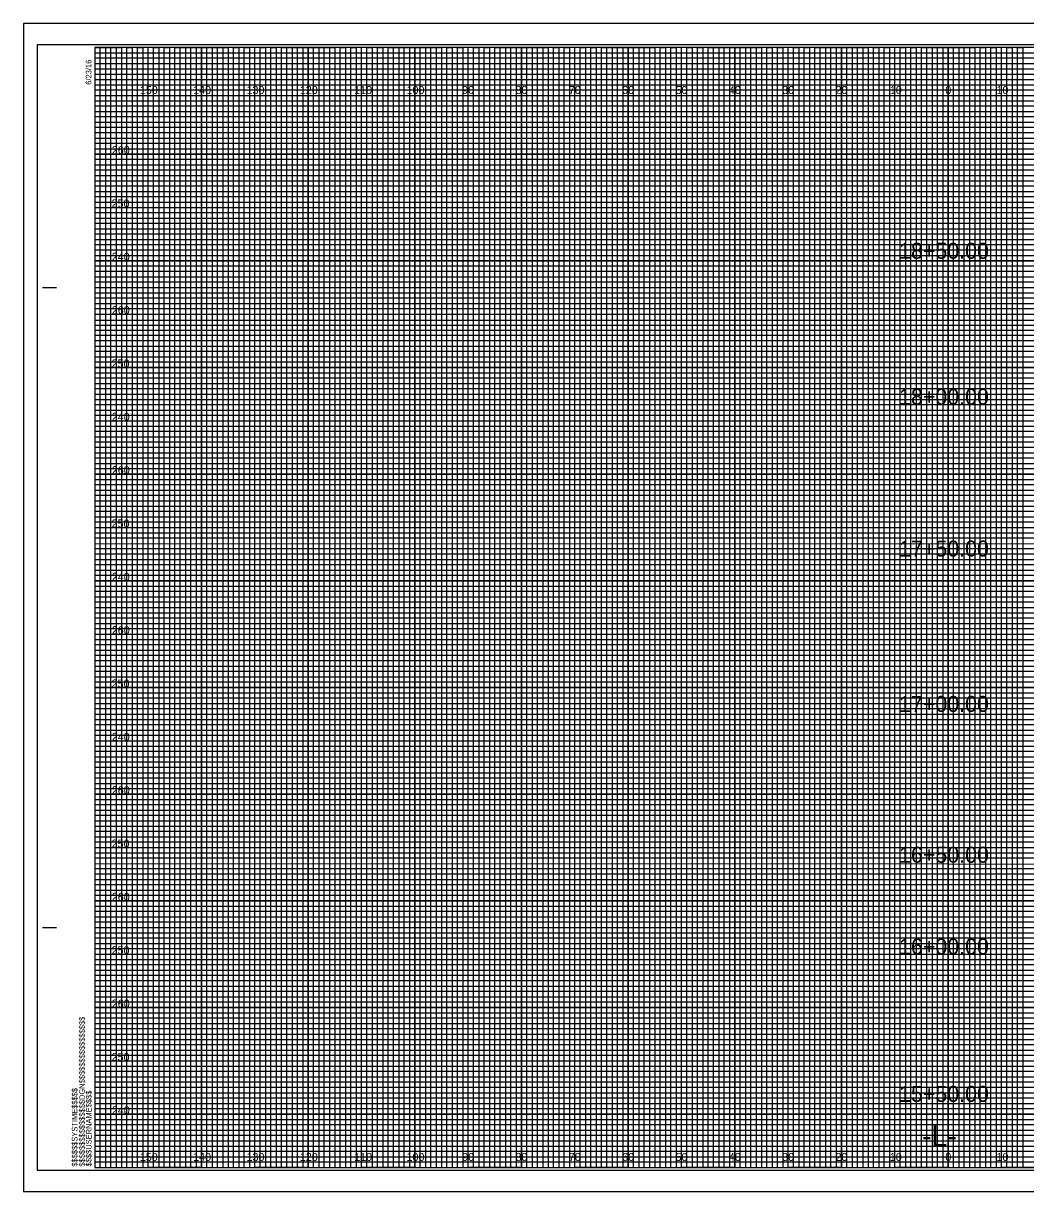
# Model space of a CAD drawing. Extents: x -13 to 359, y -5 to 2854.
# Drawn here: x -13.4 to 174.5, y -4.5 to 214.5 of the extents above; entities that cross this region are included whole.
import ezdxf

# ---------------------------------------------------------------- set-up
doc = ezdxf.new("R2010")
doc.units = 0
for name, color, linetype in [('Exist Cross Section Cell', 7, 'Continuous'), ('Exist XS Ground Line', 7, 'Continuous'), ('Prop CMT Concrete Structures', 7, 'Continuous'), ('Prop CMT DNC', 7, 'Continuous'), ('Prop CMT Pvmt Course 1', 7, 'Continuous'), ('Prop CMT Pvmt Course 1 CG', 7, 'Continuous'), ('Prop CMT Pvmt Course 2', 7, 'Continuous'), ('Prop CMT Pvmt Course 3', 7, 'Continuous'), ('Prop CMT Pvmt Course 3 Wedge', 7, 'Continuous'), ('Prop CMT Shear Line', 7, 'Continuous'), ('Prop CMT Slope Grass', 7, 'Continuous'), ('Prop CMT Subgrade Earthwork', 7, 'Continuous'), ('Scratch_Level_0', 7, 'Continuous')]:
    doc.layers.add(name, color=color, linetype=linetype)

msp = doc.modelspace()

# ---------------------------------------------------------------- linework, layer by layer
at = {"layer": 'Exist XS Ground Line'}
for p, q in [((10, 210), (0, 210)), ((10, 0), (10, 210)), ((30, 210), (20, 210)), ((20, 210), (20, 0)), ((30, 0), (30, 210)), ((50, 210), (40, 210)), ((40, 210), (40, 0)), ((50, 0), (50, 210)), ((70, 210), (60, 210)), ((60, 210), (60, 0)), ((70, 0), (70, 210)), ((90, 210), (80, 210)), ((80, 210), (80, 0)), ((90, 0), (90, 210)), ((110, 210), (100, 210)), ((100, 210), (100, 0)), ((110, 0), (110, 210)), ((130, 210), (120, 210)), ((120, 210), (120, 0)), ((130, 0), (130, 210)), ((150, 210), (140, 210)), ((140, 210), (140, 0)), ((150, 0), (150, 210)), ((170, 210), (160, 210)), ((160, 210), (160, 0)), ((170, 0), (170, 210)), ((20, 0), (10, 0)), ((40, 0), (30, 0)), ((60, 0), (50, 0)), ((80, 0), (70, 0)), ((100, 0), (90, 0)), ((120, 0), (110, 0)), ((140, 0), (130, 0)), ((160, 0), (150, 0)), ((180, 0), (170, 0))]:
    msp.add_line(p, q, dxfattribs=at)
for points in [[(0, 200), (320, 200), (320, 190), (0, 190)], [(0, 180), (320, 180), (320, 170), (0, 170)], [(0, 160), (320, 160), (320, 150), (0, 150)], [(0, 140), (320, 140), (320, 130), (0, 130)], [(0, 120), (320, 120), (320, 110), (0, 110)], [(0, 100), (320, 100), (320, 90), (0, 90)], [(0, 80), (320, 80), (320, 70), (0, 70)], [(0, 60), (320, 60), (320, 50), (0, 50)], [(0, 40), (320, 40), (320, 30), (0, 30)], [(0, 20), (320, 20), (320, 10), (0, 10)]]:
    msp.add_lwpolyline(points, dxfattribs=at)
at = {"layer": 'Prop CMT Concrete Structures'}
for p, q in [((-9.8, 165), (-7.3, 165)), ((-9.7, 165), (-7.2, 165)), ((-9.8, 45), (-7.3, 45)), ((-9.7, 45), (-7.2, 45)), ((0, 0), (0, 0)), ((0, 0), (0, 0)), ((0, 0), (0, 0)), ((0, 0), (0, 0)), ((0, 0), (0, 0)), ((0, 0), (0, 0)), ((0, 0), (0, 0))]:
    msp.add_line(p, q, dxfattribs=at)
msp.add_lwpolyline([(320, 210), (0, 210), (0, 0), (320, 0)], close=True, dxfattribs=at)
at = {"layer": 'Prop CMT DNC'}
for p, q in [((323.3, 214.5), (-13.4, 214.5)), ((-13.4, 214.5), (-13.4, -4.5)), ((-13.4, -4.5), (323.3, -4.5))]:
    msp.add_line(p, q, dxfattribs=at)
at = {"layer": 'Prop CMT Pvmt Course 1'}
for p, q in [((0, 209), (260, 209)), ((260, 207.98), (0, 207.98)), ((0, 207.98), (0, 207)), ((0, 207), (260, 207)), ((260, 205.89), (0, 205.89)), ((0, 205.89), (0, 204)), ((0, 204), (320, 204))]:
    msp.add_line(p, q, dxfattribs=at)
for points in [[(0, 203), (270, 203), (320, 203), (320, 202), (0, 202)], [(0, 201), (320, 201), (320, 199), (0, 199)], [(0, 198), (320, 198), (320, 197), (0, 196.98)], [(0, 196), (320, 196), (320, 194), (0, 194)], [(0, 193), (320, 193), (320, 192), (0, 192)], [(0, 191), (320, 191), (320, 189), (0, 189)], [(0, 188), (320, 188), (320, 187), (0, 187)], [(0, 186), (320, 186), (320, 184), (0, 184)], [(0, 183), (320, 183), (320, 182), (0, 182)], [(0, 181), (320, 181), (320, 179), (0, 179)], [(0, 178), (320, 178), (320, 177), (0, 177)], [(0, 176), (320, 176), (320, 173.95), (320, 173), (320, 172), (0, 172)], [(0, 174), (320, 174), (320, 173), (0, 173)], [(0, 171), (320, 171), (320, 169), (0, 169.03)], [(0, 169.03), (320, 169), (320, 168), (0, 168)], [(0, 167), (320, 167), (320, 166), (0, 166)], [(0, 164), (320, 164), (320, 163), (0, 163)], [(0, 162), (320, 162), (320, 161), (0, 161)], [(-0.07, 158.89), (320, 158.89), (320, 157.88), (-0.07, 157.88)], [(0, 157), (320, 157), (320, 156), (0, 156)], [(0, 154), (320, 154), (320, 153), (0, 153)], [(0, 152), (320, 152), (320, 151), (0, 151)], [(0, 149), (320, 149), (320, 148), (0, 148)], [(0, 147), (320, 147), (320, 146), (0, 146)], [(0, 144), (320, 144), (320, 143), (0, 143)], [(0, 142), (320, 142), (320, 141), (0, 141)], [(0, 139), (320, 139), (319.99, 137.98), (0, 138)], [(0, 137), (320, 137), (320, 136), (0, 136)], [(0, 134), (320, 134), (320, 133), (0, 133)], [(0, 132), (320, 132), (320, 131), (0, 131)], [(0, 129), (320, 129), (320, 128), (0, 128)], [(0, 127), (320, 127), (320, 126), (0, 126)], [(0, 124), (320, 124), (320, 123), (0, 123)], [(0, 122), (320, 122), (320, 121), (0, 121)], [(0, 119), (320, 119), (320, 118), (0, 118)], [(0, 116.99), (320.07, 116.91), (320, 116), (0, 116)], [(0, 114), (320, 114), (320, 113), (0, 113)], [(0, 112), (320, 112), (320, 111), (0, 111)], [(0, 109), (320, 109), (320, 108), (0, 108)], [(0, 107), (320, 107), (320, 106), (0, 106)], [(0, 104), (320, 104), (320, 103), (0, 103)], [(0, 102), (320, 102), (320, 101), (0, 101)], [(0, 99), (320, 99), (320, 98), (0, 98)], [(0, 97), (320, 97), (320, 96), (0, 96)], [(0, 94), (320, 94), (320, 93), (0, 93)], [(0, 92), (320, 92), (320, 91), (0, 91)], [(0, 89), (320, 89), (320, 88), (0, 88)], [(0, 87), (320, 87), (320, 86), (0, 86)], [(0, 84), (320, 84), (320, 83), (0, 83)], [(0, 82), (320, 82), (320, 81), (0, 81)], [(0, 79), (320, 79), (319.99, 77.98), (0, 78)], [(0, 77), (320, 77), (320, 76), (0, 76)], [(0, 74), (320, 74), (320, 73), (0, 73)], [(0, 72), (320, 72), (320, 71), (0, 71)], [(0, 69), (320, 69), (320, 68), (0, 68)], [(0, 67), (320, 67), (320, 66), (0, 66)], [(0, 64), (320, 64), (320, 63), (0, 63)], [(0, 62), (320, 62), (320, 61), (0, 61)], [(0, 59), (320, 59), (320, 58), (0, 58)], [(0, 56.99), (320.07, 56.91), (320, 56), (0, 56)], [(0, 54), (320, 54), (320, 53), (0, 53)], [(0, 52), (320, 52), (320, 51), (0, 51)], [(0, 49), (320, 49), (320, 48), (0, 48)], [(0, 47), (320, 47), (320, 46), (0, 46)], [(0, 44), (320, 44), (320, 43), (0, 43)], [(0, 42), (320, 42), (320, 41), (0, 41)], [(0, 39), (320, 39), (320, 38), (0, 38)], [(0, 37), (320, 37), (320, 36), (0, 36)], [(0, 34), (320, 34), (320, 33), (0, 33)], [(0, 32), (320, 32), (320, 31), (0, 31)], [(0, 29), (320, 29), (320, 28), (0, 28)], [(0, 27), (320, 27), (320, 26), (0, 26)], [(0, 24), (320, 24), (320, 23), (0, 23)], [(0, 22), (320, 22), (320, 21), (0, 21)], [(0, 19), (320, 19), (320, 18), (0, 18)], [(0, 17), (320, 17), (320, 16), (0, 16)], [(0, 14), (320, 14), (320, 13), (0, 13)], [(0, 12), (320, 12), (320, 11), (0, 11)], [(0, 9), (320, 9), (320, 8), (0, 8)], [(0, 7), (320, 7), (320, 6), (0, 6)], [(0, 4), (320, 4), (320, 3), (0, 3)], [(0, 2), (320, 2), (320, 1), (0, 1)]]:
    msp.add_lwpolyline(points, dxfattribs=at)
at = {"layer": 'Prop CMT Pvmt Course 1 CG'}
for points in [[(0, 0), (1, 0), (1, 210), (2, 210), (2, 0)], [(2, 0), (3, 0), (3, 210), (4, 210), (4, 0)], [(5, 0), (6, 0), (6, 210), (7, 210), (7, 0)], [(7, 0), (8, 0), (8, 210), (9, 210), (9, 0)], [(10, 0), (11, 0), (11, 210), (12, 210), (12, 0)], [(12, 0), (13, 0), (13, 210), (14, 210), (14, 0)], [(15, 0), (16, 0), (16, 210), (17, 210), (17, 0)], [(17, 0), (18, 0), (18, 210), (19, 210), (19, 0)], [(20, 0), (21, 0), (21, 210), (22, 210), (22, 0)], [(22, 0), (23, 0), (23, 210), (24, 210), (24, 0)], [(25, 0), (26, 0), (26, 210), (27, 210), (27, 0)], [(27, 0), (28, 0), (28, 210), (29, 210), (29, 0)], [(30, 0), (31, 0), (31, 210), (32, 210), (32, 0)], [(32, 0), (33, 0), (33, 210), (34, 210), (34, 0)], [(35, 0), (36, 0), (36, 210), (37, 210), (37, 0)], [(37, 0), (38, 0), (38, 210), (39, 210), (39, 0)], [(40, 0), (41, 0), (41, 210), (42, 210), (42, 0)], [(42, 0), (43, 0), (43, 210), (44, 210), (44, 0)], [(45, 0), (46, 0), (46, 210), (47, 210), (47, 0)], [(47, 0), (48, 0), (48, 210), (49, 210), (49, 0)], [(50, 0), (51, 0), (51, 210), (52, 210), (52, 0)], [(52, 0), (53, 0), (53, 210), (54, 210), (54, 0)], [(55, 0), (56, 0), (56, 210), (57, 210), (57, 0)], [(57, 0), (58, 0), (58, 210), (59, 210), (59, 0)], [(60, 0), (61, 0), (61, 210), (62, 210), (62, 0)], [(62, 0), (63, 0), (63, 210), (64, 210), (64, 0)], [(65, 0), (66, 0), (66, 210), (67, 210), (67, 0)], [(67, 0), (68, 0), (68, 210), (69, 210), (69, 0)], [(70, 0), (71, 0), (71, 210), (72, 210), (72, 0)], [(72, 0), (73, 0), (73, 210), (74, 210), (74, 0)], [(75, 0), (76, 0), (76, 210), (77, 210), (77, 0)], [(77, 0), (78, 0), (78, 210), (79, 210), (79, 0)], [(80, 0), (81, 0), (81, 210), (82, 210), (82, 0)], [(82, 0), (83, 0), (83, 210), (84, 210), (84, 0)], [(85, 0), (86, 0), (86, 210), (87, 210), (87, 0)], [(87, 0), (88, 0), (88, 210), (89, 210), (89, 0)], [(90, 0), (91, 0), (91, 210), (92, 210), (92, 0)], [(92, 0), (93, 0), (93, 210), (94, 210), (94, 0)], [(95, 0), (96, 0), (96, 210), (97, 210), (97, 0)], [(97, 0), (98, 0), (98, 210), (99, 210), (99, 0)], [(100, 0), (101, 0), (101, 210), (102, 210), (102, 0)], [(102, 0), (103, 0), (103, 210), (104, 210), (104, 0)], [(105, 0), (106, 0), (106, 210), (107, 210), (107, 0)], [(107, 0), (108, 0), (108, 210), (109, 210), (109, 0)], [(110, 0), (111, 0), (111, 210), (112, 210), (112, 0)], [(112, 0), (113, 0), (113, 210), (114, 210), (114, 0)], [(115, 0), (116, 0), (116, 210), (117, 210), (117, 0)], [(117, 0), (118, 0), (118, 210), (119, 210), (119, 0)], [(120, 0), (121, 0), (121, 210), (122, 210), (122, 0)], [(122, 0), (123, 0), (123, 210), (124, 210), (124, 0)], [(125, 0), (126, 0), (126, 210), (127, 210), (127, 0)], [(127, 0), (128, 0), (128, 210), (129, 210), (129, 0)], [(130, 0), (131, 0), (131, 210), (132, 210), (132, 0)], [(132, 0), (133, 0), (133, 210), (134, 210), (134, 0)], [(135, 0), (136, 0), (136, 210), (137, 210), (137, 0)], [(137, 0), (138, 0), (138, 210), (139, 210), (139, 0)], [(140, 0), (141, 0), (141, 210), (142, 210), (142, 0)], [(142, 0), (143, 0), (143, 210), (144, 210), (144, 0)], [(145, 0), (146, 0), (146, 210), (147, 210), (147, 0)], [(147, 0), (148, 0), (148, 210), (149, 210), (149, 0)], [(150, 0), (151, 0), (151, 210), (152, 210), (152, 0)], [(152, 0), (153, 0), (153, 210), (154, 210), (154, 0)], [(155, 0), (156, 0), (156, 210), (157, 210), (157, 0)], [(157, 0), (158, 0), (158, 210), (159, 210), (159, 0)], [(160, 0), (161, 0), (161, 210), (162, 210), (162, 0)], [(162, 0), (163, 0), (163, 210), (164, 210), (164, 0)], [(165, 0), (166, 0), (166, 210), (167, 210), (167, 0)], [(167, 0), (168, 0), (168, 210), (169, 210), (169, 0)], [(170, 0), (171, 0), (171, 210), (172, 210), (172, 0)], [(172, 0), (173, 0), (173, 210), (174, 210), (174, 0)]]:
    msp.add_lwpolyline(points, dxfattribs=at)
at = {"layer": 'Prop CMT Shear Line'}
for p, q in [((10, 0), (10, 210)), ((20, 0), (20, 210)), ((30, 0), (30, 210)), ((40, 0), (40, 210)), ((50, 0), (50, 210)), ((60, 0), (60, 210)), ((70, 0), (70, 210)), ((80, 0), (80, 210)), ((90, 0), (90, 210)), ((100, 0), (100, 210)), ((110, 0), (110, 210)), ((120, 0), (120, 210)), ((130, 0), (130, 210)), ((140, 0), (140, 210)), ((150, 0), (150, 210)), ((160, 0), (160, 210)), ((170, 0), (170, 210)), ((0, 200), (320, 200)), ((0, 190), (320, 190)), ((0, 180), (320, 180)), ((0, 170), (320, 170)), ((0, 160), (320, 160)), ((0, 150), (320, 150)), ((0, 140), (320, 140)), ((0, 130), (320, 130)), ((0, 120), (320, 120)), ((0, 110), (320, 110)), ((0, 100), (320, 100)), ((0, 90), (320, 90)), ((0, 80), (320, 80)), ((0, 70), (320, 70)), ((0, 60), (320, 60)), ((0, 50), (320, 50)), ((0, 40), (320, 40)), ((0, 30), (320, 30)), ((0, 20), (320, 20)), ((0, 10), (320, 10))]:
    msp.add_line(p, q, dxfattribs=at)
at = {"layer": 'Prop CMT Slope Grass'}
msp.add_lwpolyline([(-10.8, -0.5), (322.4, -0.5), (322.4, 210.5), (-10.8, 210.5)], close=True, dxfattribs=at)
at = {"layer": 'Prop CMT Subgrade Earthwork'}
msp.add_lwpolyline([(-13.4, -4.5), (323.3, -4.5), (323.3, 214.5), (-13.4, 214.5)], close=True, dxfattribs=at)
at = {"layer": 'Scratch_Level_0'}
for points in [[(0, 210), (5, 210), (5, 0), (15, 0), (15, 210), (25, 210), (25, 0), (35, 0), (35, 210), (45, 210), (45, 0), (55, 0), (55, 210), (65, 210), (65, 0), (75, 0), (75, 210), (85, 210), (85, 0), (95, 0), (95, 210), (105, 210), (105, 0), (115, 0), (115, 210), (125, 210), (125, 0), (135, 0), (135, 210), (145, 210), (145, 0), (155, 0), (155, 210), (165, 210), (165, 0), (175, 0)], [(0, 205), (275, 205)], [(0, 185), (320, 185), (320, 195), (0, 195)], [(0, 165), (320, 165), (320, 175), (0, 175)], [(0, 145), (320, 145), (320, 155), (0, 155)], [(0, 125), (320, 125), (320, 135), (0, 135)], [(0, 105), (320, 105), (320, 115), (0, 115)], [(0, 85), (320, 85), (320, 95), (0, 95)], [(0, 65), (320, 65), (320, 75), (0, 75)], [(0, 45), (320, 45), (320, 55), (0, 55)], [(0, 25), (320, 25), (320, 35), (0, 35)], [(0, 5), (320, 5), (320, 15), (0, 15)]]:
    msp.add_lwpolyline(points, dxfattribs=at)

# ---------------------------------------------------------------- texts
at = {"layer": 'Exist Cross Section Cell'}
for s, p in [('150', (8.44, 201.25)), ('140', (18.44, 201.25)), ('130', (28.44, 201.25)), ('120', (38.44, 201.25)), ('110', (48.62, 201.25)), ('100', (58.44, 201.25)), ('90', (68.86, 201.25)), ('80', (78.86, 201.25)), ('70', (88.86, 201.25)), ('60', (98.86, 201.25)), ('50', (108.86, 201.25)), ('40', (118.86, 201.25)), ('30', (128.86, 201.25)), ('20', (138.86, 201.25)), ('10', (149.04, 201.25)), ('0', (159.45, 201.25)), ('0', (159.45, 201.25)), ('10', (169.04, 201.25)), ('150', (8.44, 1.25)), ('140', (18.44, 1.25)), ('130', (28.44, 1.25)), ('120', (38.44, 1.25)), ('110', (48.62, 1.25)), ('100', (58.44, 1.25)), ('90', (68.86, 1.25)), ('80', (78.86, 1.25)), ('70', (88.86, 1.25)), ('60', (98.86, 1.25)), ('50', (108.86, 1.25)), ('40', (118.86, 1.25)), ('30', (128.86, 1.25)), ('20', (138.86, 1.25)), ('10', (149.04, 1.25)), ('0', (159.45, 1.25)), ('0', (159.45, 1.25)), ('10', (169.04, 1.25))]:
    msp.add_text(s, height=1.5, dxfattribs=at).set_placement(p)
at = {"layer": 'Prop CMT Concrete Structures'}
for s, p in [('6/23/16', (-0.65, 203)), ('$$$$$$$$$$$$$$$$DGN$$$$$$$$$$$$$$$$', (-1.88, 0.18)), ('$$$$$$SYSTIME$$$$$', (-3.26, 0.18)), ('$$$$USERNAME$$$$', (-0.62, 0.23))]:
    msp.add_text(s, height=1.05, rotation=90, dxfattribs=at).set_placement(p)
at = {"layer": 'Prop CMT Pvmt Course 2'}
for s, p in [('260', (3.19, 190)), ('250', (3.15, 180)), ('240', (3.19, 170)), ('260', (3.19, 160)), ('250', (3.15, 150)), ('240', (3.19, 140)), ('260', (3.19, 130)), ('250', (3.15, 120)), ('240', (3.19, 110)), ('260', (3.19, 100)), ('250', (3.15, 90)), ('240', (3.19, 80)), ('260', (3.19, 70)), ('250', (3.15, 60)), ('260', (3.19, 50)), ('250', (3.15, 40)), ('260', (3.19, 30)), ('250', (3.15, 20)), ('240', (3.19, 10))]:
    msp.add_text(s, height=1.5, dxfattribs=at).set_placement(p)
at = {"layer": 'Prop CMT Pvmt Course 3'}
for s, p in [('18+50.00', (150.77, 170.37)), ('18+00.00', (150.77, 143.02)), ('17+50.00', (150.77, 114.54)), ('17+00.00', (150.77, 85.42)), ('16+50.00', (150.77, 57.16)), ('16+00.00', (150.77, 39.96)), ('15+50.00', (150.77, 12.33))]:
    msp.add_text(s, height=3, dxfattribs=at).set_placement(p)
at = {"layer": 'Prop CMT Pvmt Course 3 Wedge'}
msp.add_text('-L-', height=4, dxfattribs=at).set_placement((155.06, 4))

doc.saveas('drawing.dxf')
